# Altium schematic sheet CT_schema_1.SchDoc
size 389 x 258 mm
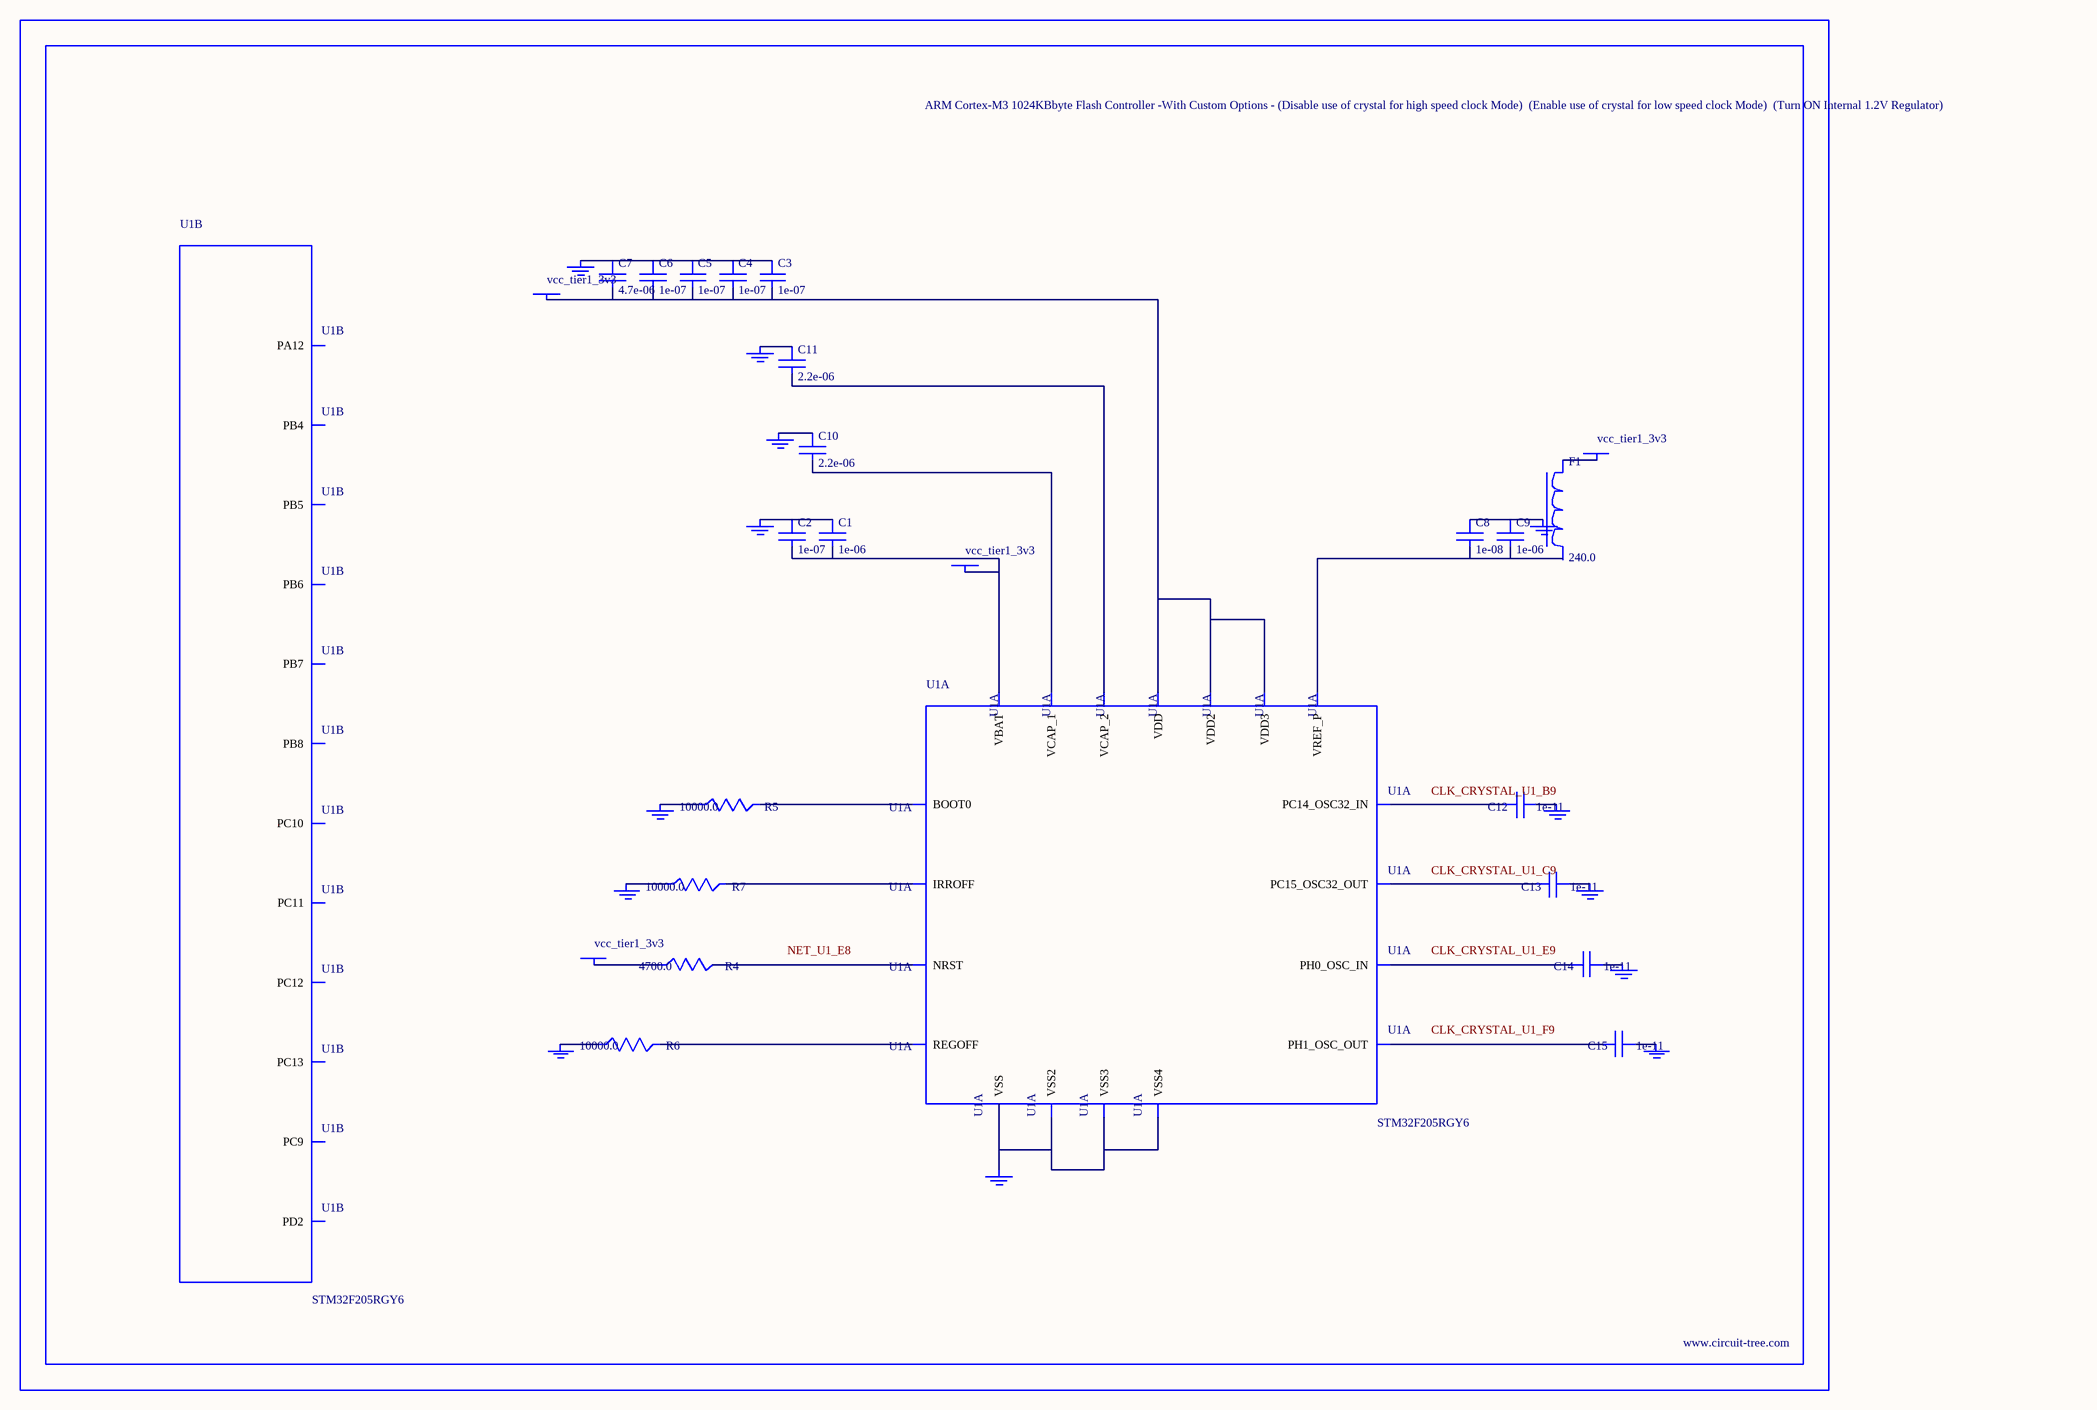
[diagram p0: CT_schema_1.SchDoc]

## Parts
BORDER0  (no value)
C1  1e-06  [C0603]
C2  1e-07  [C0603]
C3  1e-07  [C0603]
C4  1e-07  [C0603]
C5  1e-07  [C0603]
C6  1e-07  [C0603]
C7  4.7e-06  [C0603]
C8  1e-08  [C0603]
C9  1e-06  [C0603]
C10  2.2e-06  [C0603]
C11  2.2e-06  [C0603]
C12  1e-11  [C0402]
C13  1e-11  [C0402]
C14  1e-11  [C0402]
C15  1e-11  [C0402]
F1  240.0  [L0603]
GND_INSTANCE_0_0  (no value)
GND_INSTANCE_0_1  (no value)
GND_INSTANCE_0_2  (no value)
GND_INSTANCE_0_3  (no value)
GND_INSTANCE_0_4  (no value)
GND_INSTANCE_0_5  (no value)
GND_INSTANCE_0_6  (no value)
GND_INSTANCE_0_7  (no value)
GND_INSTANCE_0_8  (no value)
GND_INSTANCE_0_9  (no value)
GND_INSTANCE_0_10  (no value)
GND_INSTANCE_0_11  (no value)
GND_INSTANCE_0_12  (no value)
POWER_INSTANCE_0_0  vcc_tier1_3v3
POWER_INSTANCE_0_1  vcc_tier1_3v3
POWER_INSTANCE_0_2  vcc_tier1_3v3
POWER_INSTANCE_0_3  vcc_tier1_3v3
R4  4700.0  [R0603]
R5  10000.0  [R0603]
R6  10000.0  [R0603]
R7  10000.0  [R0603]
U1  STM32F205RGY6  [WLCSP66]  (parts A,B of 6)

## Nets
NetC1_1: C1.1 C2.1 GND_INSTANCE_0_0.0(GND)
NetC1_2: C1.2 C2.2 POWER_INSTANCE_0_0.0(PWR) U1.A9(VBAT)
NetC3_1: C3.1 C4.1 C5.1 C6.1 C7.1 GND_INSTANCE_0_1.0(GND)
NetC3_2: C3.2 C4.2 C5.2 C6.2 C7.2 POWER_INSTANCE_0_1.0(PWR) U1.A8(VDD) U1.D9(VDD2) U1.E1(VDD3)
NetC8_1: C8.1 C9.1 GND_INSTANCE_0_3.0(GND)
NetC8_2: C8.2 C9.2 U1.F7(VREF_P)
NetC10_1: C10.1 GND_INSTANCE_0_6.0(GND)
NetC10_2: C10.2 U1.J3(VCAP_1)
NetC11_1: C11.1 GND_INSTANCE_0_7.0(GND)
NetC11_2: C11.2 U1.C2(VCAP_2)
NetC12_1: C12.1 GND_INSTANCE_0_8.0(GND)
NetC12_2: C12.2 U1.B9(PC14_OSC32_IN)
NetC13_1: C13.1 GND_INSTANCE_0_9.0(GND)
NetC13_2: C13.2 U1.C9(PC15_OSC32_OUT)
NetC14_1: C14.1 GND_INSTANCE_0_10.0(GND)
NetC14_2: C14.2 U1.E9(PH0_OSC_IN)
NetC15_1: C15.1 GND_INSTANCE_0_11.0(GND)
NetC15_2: C15.2 U1.F9(PH1_OSC_OUT)
NetF1_1: F1.1 POWER_INSTANCE_0_2.0(PWR)
NetGND_INSTANCE_0_2_0: GND_INSTANCE_0_2.0(GND) R5.1
NetGND_INSTANCE_0_4_0: GND_INSTANCE_0_4.0(GND) R6.1
NetGND_INSTANCE_0_5_0: GND_INSTANCE_0_5.0(GND) R7.1
NetGND_INSTANCE_0_12_0: GND_INSTANCE_0_12.0(GND) U1.B1(VSS) U1.D8(VSS2) U1.F1(VSS3) U1.H9(VSS4)
NetPOWER_INSTANCE_0_3_0: POWER_INSTANCE_0_3.0(PWR) R4.1
NetR4_2: R4.2 U1.E8(NRST)
NetR5_2: R5.2 U1.B6(BOOT0)
NetR6_2: R6.2 U1.H7(REGOFF)
NetR7_2: R7.2 U1.C8(IRROFF)

Not connected (* = marked no-connect by the designer): F1 2; U1 A3(PC12) A5(PB5) A6(PB7) B3(PC10) B4(PB4) B5(PB6) B7(PB8) B8(PC13) C1(PA12) C3(PC11) C7(PD2) D1(PC9)

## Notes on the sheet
- Labels drawn without touching a wire or pin: CLK_CRYSTAL_U1_B9, CLK_CRYSTAL_U1_C9, CLK_CRYSTAL_U1_E9, CLK_CRYSTAL_U1_F9, NET_U1_E8

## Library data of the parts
BORDER0 = BORDER_PAGE0
C1 C9 = C0603C105K3RACTU
C2-C6 = 06035C104K4Z2A
C7 = GRM188R6YA475KE15D
C8 = 06035C103K4Z2A
C10 C11 = C0603C225K8RACTU
C12-C15 = C0402C100K3GACTU
F1 = Z0603C241ASMST
GND_INSTANCE_0_0-GND_INSTANCE_0_12 = GND
POWER_INSTANCE_0_0-POWER_INSTANCE_0_3 = PWR
R4 = RC0603JR-074K7L
R5-R7 = RC0603JR-0710KL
